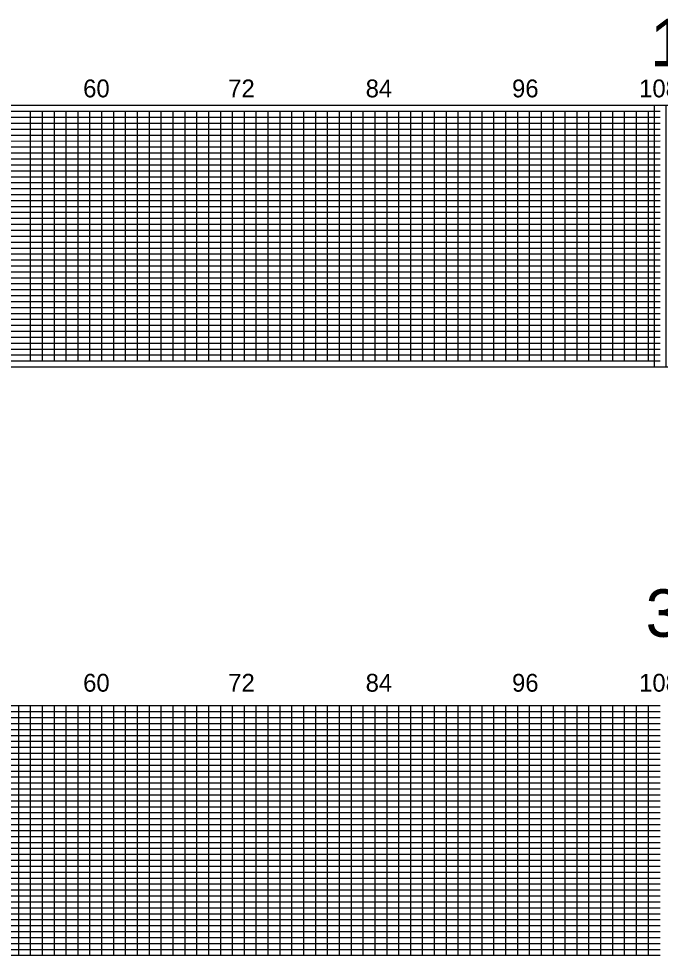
# Model space of a CAD drawing. Extents: x 1870112 to 1888282, y 758439 to 777406.
# Drawn here: x 1880232 to 1882932, y 773464 to 777403 of the extents above; entities that cross this region are included whole.
import ezdxf

# ---------------------------------------------------------------- set-up
doc = ezdxf.new("R2010")
doc.units = 0
for name, color, linetype in [('RD_PD_WallFill', 7, 'Continuous'), ('RD_SHT_IplotShp', 7, 'Continuous'), ('RD_Sketch8', 7, 'Continuous')]:
    doc.layers.add(name, color=color, linetype=linetype)

msp = doc.modelspace()

# ---------------------------------------------------------------- linework, layer by layer
at = {"layer": 'RD_PD_WallFill'}
for p, q in [((1877581.6, 777014.1), (1882931.6, 777014.2)), ((1880281.6, 775964.2), (1880281.6, 777014.2)), ((1880331.6, 775964.2), (1880331.6, 777014.2)), ((1880381.6, 775964.2), (1880381.6, 777014.2)), ((1880431.6, 775964.2), (1880431.6, 777014.2)), ((1880481.6, 775964.2), (1880481.6, 777014.2)), ((1880531.6, 775964.2), (1880531.6, 777014.2)), ((1880581.6, 775964.2), (1880581.6, 777014.2)), ((1880631.6, 775964.2), (1880631.6, 777014.2)), ((1880681.6, 775964.1), (1880681.6, 777014.2)), ((1880731.6, 775964.2), (1880731.6, 777014.2)), ((1880781.6, 775964.2), (1880781.6, 777014.2)), ((1880831.6, 775964.2), (1880831.6, 777014.2)), ((1880881.6, 775964.2), (1880881.6, 777014.2)), ((1880931.6, 775964.2), (1880931.6, 777014.2)), ((1880981.6, 775964.1), (1880981.6, 777014.2)), ((1881031.6, 775964.1), (1881031.6, 777014.2)), ((1881081.6, 775964.2), (1881081.6, 777014.2)), ((1881131.6, 775964.2), (1881131.6, 777014.2)), ((1881181.6, 775964.2), (1881181.6, 777014.2)), ((1881231.6, 775964.2), (1881231.6, 777014.2)), ((1881281.6, 775964.2), (1881281.6, 777014.2)), ((1881331.6, 775964.2), (1881331.6, 777014.2)), ((1881381.6, 775964.2), (1881381.6, 777014.2)), ((1881431.6, 775964.2), (1881431.6, 777014.2)), ((1881481.6, 775964.2), (1881481.6, 777014.2)), ((1881531.6, 775964.2), (1881531.6, 777014.2)), ((1881581.6, 775964.2), (1881581.6, 777014.2)), ((1881631.6, 775964.2), (1881631.6, 777014.2)), ((1881681.6, 775964.2), (1881681.6, 777014.2)), ((1881731.6, 775964.2), (1881731.6, 777014.2)), ((1881781.6, 775964.2), (1881781.6, 777014.2)), ((1881831.6, 775964.2), (1881831.6, 777014.2)), ((1881881.6, 775964.2), (1881881.6, 777014.2)), ((1881931.6, 775964.2), (1881931.6, 777014.2)), ((1881981.6, 775964.2), (1881981.6, 777014.2)), ((1882031.6, 775964.2), (1882031.6, 777014.2)), ((1882081.6, 775964.2), (1882081.6, 777014.2)), ((1882131.6, 775964.2), (1882131.6, 777014.2)), ((1882181.6, 775964.2), (1882181.6, 777014.2)), ((1882231.6, 775964.2), (1882231.6, 777014.2)), ((1882281.6, 775964.2), (1882281.6, 777014.2)), ((1882331.6, 775964.2), (1882331.6, 777014.2)), ((1882381.6, 775964.2), (1882381.6, 777014.2)), ((1882431.6, 775964.2), (1882431.6, 777014.2)), ((1882481.6, 775964.2), (1882481.6, 777014.2)), ((1882531.6, 775964.2), (1882531.6, 777014.2)), ((1882581.6, 775964.2), (1882581.6, 777014.2)), ((1882631.6, 775964.2), (1882631.6, 777014.2)), ((1882681.6, 775964.2), (1882681.6, 777014.2)), ((1882731.6, 775964.2), (1882731.6, 777014.2)), ((1882781.6, 775964.2), (1882781.6, 777014.2)), ((1882831.6, 775964.2), (1882831.6, 777014.2)), ((1882881.6, 775964.2), (1882881.6, 777014.2)), ((1878031.6, 776989.1), (1882931.6, 776989.1)), ((1878031.6, 776964.1), (1882931.6, 776964.1)), ((1878031.6, 776939.1), (1882931.6, 776939.1)), ((1878031.6, 776914.2), (1882931.6, 776914.1)), ((1878031.6, 776889.1), (1882931.6, 776889.2)), ((1877581.6, 776864.1), (1882931.6, 776864.1)), ((1877581.6, 776839.1), (1882931.6, 776839.1)), ((1877581.6, 776814.1), (1882931.6, 776814.2)), ((1877581.6, 776789.2), (1882931.6, 776789.1)), ((1877581.6, 776764.2), (1882931.6, 776764.2)), ((1877581.6, 776739.1), (1882931.6, 776739.1)), ((1877581.6, 776714.1), (1882931.6, 776714.1)), ((1877581.6, 776689.2), (1882931.6, 776689.1)), ((1877581.6, 776664.1), (1882931.6, 776664.1)), ((1877581.6, 776639.2), (1882931.6, 776639.1)), ((1877581.6, 776614.1), (1882931.6, 776614.1)), ((1877581.6, 776589.1), (1882931.6, 776589.2)), ((1877581.6, 776564.1), (1882931.6, 776564.1)), ((1877581.6, 776539.1), (1882931.6, 776539.2)), ((1877581.6, 776514.1), (1882931.6, 776514.1)), ((1877581.6, 776489.1), (1882931.6, 776489.1)), ((1877581.6, 776464.2), (1882931.6, 776464.1)), ((1877581.6, 776439.1), (1882931.6, 776439.1)), ((1877581.6, 776414.1), (1882931.6, 776414.1)), ((1877581.6, 776389.1), (1882931.6, 776389.1)), ((1877581.6, 776364.1), (1882931.6, 776364.2)), ((1877581.6, 776339.1), (1882931.6, 776339.1)), ((1877581.6, 776314.1), (1882931.6, 776314.1)), ((1877581.6, 776289.1), (1882931.6, 776289.1)), ((1877581.6, 776264.1), (1882931.6, 776264.1)), ((1877581.6, 776239.1), (1882931.6, 776239.1)), ((1877581.6, 776214.1), (1882931.6, 776214.1)), ((1877581.6, 776189.1), (1882931.6, 776189.1)), ((1877581.6, 776164.1), (1882931.6, 776164.1)), ((1877581.6, 776139.1), (1882931.6, 776139.1)), ((1877581.6, 776114.1), (1882931.6, 776114.1)), ((1877581.6, 776089.1), (1882931.6, 776089.1)), ((1877581.6, 776064.1), (1882931.6, 776064.1)), ((1877581.6, 776039.1), (1882931.6, 776039.1)), ((1877581.6, 776014.1), (1882931.6, 776014.1)), ((1877631.6, 775989.1), (1882931.6, 775989.1)), ((1877581.6, 775964.1), (1882931.6, 775964.1)), ((1877581.6, 774514.1), (1882931.6, 774514.2)), ((1878031.6, 774489.1), (1882931.6, 774489.1)), ((1880231.6, 773464.2), (1880231.6, 774514.2)), ((1880281.6, 773464.2), (1880281.6, 774514.2)), ((1880331.6, 773464.2), (1880331.6, 774514.2)), ((1880381.6, 773464.2), (1880381.6, 774514.2)), ((1880431.6, 773464.2), (1880431.6, 774514.2)), ((1880481.6, 773464.2), (1880481.6, 774514.2)), ((1880531.6, 773464.2), (1880531.6, 774514.2)), ((1880581.6, 773464.2), (1880581.6, 774514.2)), ((1880631.6, 773464.2), (1880631.6, 774514.2)), ((1880681.6, 773464.1), (1880681.6, 774514.2)), ((1880731.6, 773464.2), (1880731.6, 774514.2)), ((1880781.6, 773464.2), (1880781.6, 774514.2)), ((1880831.6, 773464.2), (1880831.6, 774514.2)), ((1880881.6, 773464.2), (1880881.6, 774514.2)), ((1880931.6, 773464.2), (1880931.6, 774514.2)), ((1880981.6, 773464.1), (1880981.6, 774514.2)), ((1881031.6, 773464.1), (1881031.6, 774514.2)), ((1881081.6, 773464.2), (1881081.6, 774514.2)), ((1881131.6, 773464.2), (1881131.6, 774514.2)), ((1881181.6, 773464.2), (1881181.6, 774514.2)), ((1881231.6, 773464.2), (1881231.6, 774514.2)), ((1881281.6, 773464.2), (1881281.6, 774514.2)), ((1881331.6, 773464.2), (1881331.6, 774514.2)), ((1881381.6, 773464.2), (1881381.6, 774514.2)), ((1881431.6, 773464.2), (1881431.6, 774514.2)), ((1881481.6, 773464.2), (1881481.6, 774514.2)), ((1881531.6, 773464.2), (1881531.6, 774514.2)), ((1881581.6, 773464.2), (1881581.6, 774514.2)), ((1881631.6, 773464.2), (1881631.6, 774514.2)), ((1881681.6, 773464.2), (1881681.6, 774514.2)), ((1881731.6, 773464.2), (1881731.6, 774514.2)), ((1881781.6, 773464.2), (1881781.6, 774514.2)), ((1881831.6, 773464.2), (1881831.6, 774514.2)), ((1881881.6, 773464.2), (1881881.6, 774514.2)), ((1881931.6, 773464.2), (1881931.6, 774514.2)), ((1881981.6, 773464.2), (1881981.6, 774514.2)), ((1882031.6, 773464.2), (1882031.6, 774514.2)), ((1882081.6, 773464.2), (1882081.6, 774514.2)), ((1882131.6, 773464.2), (1882131.6, 774514.2)), ((1882181.6, 773464.2), (1882181.6, 774514.2)), ((1882231.6, 773464.2), (1882231.6, 774514.2)), ((1882281.6, 773464.2), (1882281.6, 774514.2)), ((1882331.6, 773464.2), (1882331.6, 774514.2)), ((1882381.6, 773464.2), (1882381.6, 774514.2)), ((1882431.6, 773464.2), (1882431.6, 774514.2)), ((1882481.6, 773464.2), (1882481.6, 774514.2)), ((1882531.6, 773464.2), (1882531.6, 774514.2)), ((1882581.6, 773464.2), (1882581.6, 774514.2)), ((1882631.6, 773464.2), (1882631.6, 774514.2)), ((1882681.6, 773464.2), (1882681.6, 774514.2)), ((1882731.6, 773464.2), (1882731.6, 774514.2)), ((1882781.6, 773464.2), (1882781.6, 774514.2)), ((1882831.6, 773464.2), (1882831.6, 774514.2)), ((1882881.6, 773464.2), (1882881.6, 774514.2)), ((1878031.6, 774464.1), (1882931.6, 774464.1)), ((1878031.6, 774439.1), (1882931.6, 774439.1)), ((1878031.6, 774414.2), (1882931.6, 774414.1)), ((1877581.6, 774364.1), (1882931.6, 774364.1)), ((1878031.6, 774389.1), (1882931.6, 774389.2)), ((1877581.6, 774339.1), (1882931.6, 774339.1)), ((1877581.6, 774314.1), (1882931.6, 774314.2)), ((1877581.6, 774289.2), (1882931.6, 774289.1)), ((1877581.6, 774264.2), (1882931.6, 774264.2)), ((1877581.6, 774239.1), (1882931.6, 774239.1)), ((1877581.6, 774214.1), (1882931.6, 774214.1)), ((1877581.6, 774189.2), (1882931.6, 774189.1)), ((1877581.6, 774164.1), (1882931.6, 774164.1)), ((1877581.6, 774139.2), (1882931.6, 774139.1)), ((1877581.6, 774114.1), (1882931.6, 774114.1)), ((1877581.6, 774089.1), (1882931.6, 774089.2)), ((1877581.6, 774064.1), (1882931.6, 774064.1)), ((1877581.6, 774039.1), (1882931.6, 774039.2)), ((1877581.6, 774014.1), (1882931.6, 774014.1)), ((1877581.6, 773989.1), (1882931.6, 773989.1)), ((1877581.6, 773964.2), (1882931.6, 773964.1)), ((1877581.6, 773939.1), (1882931.6, 773939.1)), ((1877581.6, 773914.1), (1882931.6, 773914.1)), ((1877581.6, 773889.1), (1882931.6, 773889.1)), ((1877581.6, 773864.1), (1882931.6, 773864.2)), ((1877581.6, 773839.1), (1882931.6, 773839.1)), ((1877581.6, 773814.1), (1882931.6, 773814.1)), ((1877581.6, 773789.1), (1882931.6, 773789.1)), ((1877581.6, 773764.1), (1882931.6, 773764.1)), ((1877581.6, 773739.1), (1882931.6, 773739.1)), ((1877581.6, 773714.1), (1882931.6, 773714.1)), ((1877581.6, 773689.1), (1882931.6, 773689.1)), ((1877581.6, 773664.1), (1882931.6, 773664.1)), ((1877581.6, 773639.1), (1882931.6, 773639.1)), ((1877581.6, 773614.1), (1882931.6, 773614.1)), ((1877581.6, 773589.1), (1882931.6, 773589.1)), ((1877581.6, 773564.1), (1882931.6, 773564.1)), ((1877581.6, 773539.1), (1882931.6, 773539.1)), ((1877581.6, 773514.1), (1882931.6, 773514.1)), ((1877581.6, 773464.1), (1882931.6, 773464.1)), ((1877631.6, 773489.1), (1882931.6, 773489.1))]:
    msp.add_line(p, q, dxfattribs=at)
at = {"layer": 'RD_SHT_IplotShp'}
for points in [[(1877556.6, 775939.1), (1882956.6, 775939.1), (1882956.6, 777039.1), (1877556.6, 777039.1)], [(1882906.6, 775939.2), (1884656.6, 775939.2), (1884656.6, 777039.2), (1882906.6, 777039.2)]]:
    msp.add_lwpolyline(points, close=True, dxfattribs=at)

# ---------------------------------------------------------------- texts
at = {"layer": 'RD_PD_WallFill'}
for s, p in [('60', (1880502.8, 777072.8)), ('72', (1881113.4, 777072.8)), ('84', (1881691.7, 777072.8)), ('96', (1882307.8, 777072.8)), ('108', (1882842.8, 777072.8)), ('60', (1880502.8, 774572.8)), ('72', (1881113.5, 774572.8)), ('84', (1881691.7, 774572.8)), ('96', (1882307.8, 774572.8)), ('108', (1882842.8, 774572.8))]:
    msp.add_text(s, height=75, dxfattribs=at).set_placement(p)
at = {"layer": 'RD_Sketch8'}
for s, p in [('1', (1882889.3, 777203.5)), ('3', (1882870, 774803.5))]:
    msp.add_text(s, height=200, dxfattribs=at).set_placement(p)

doc.saveas('drawing.dxf')
